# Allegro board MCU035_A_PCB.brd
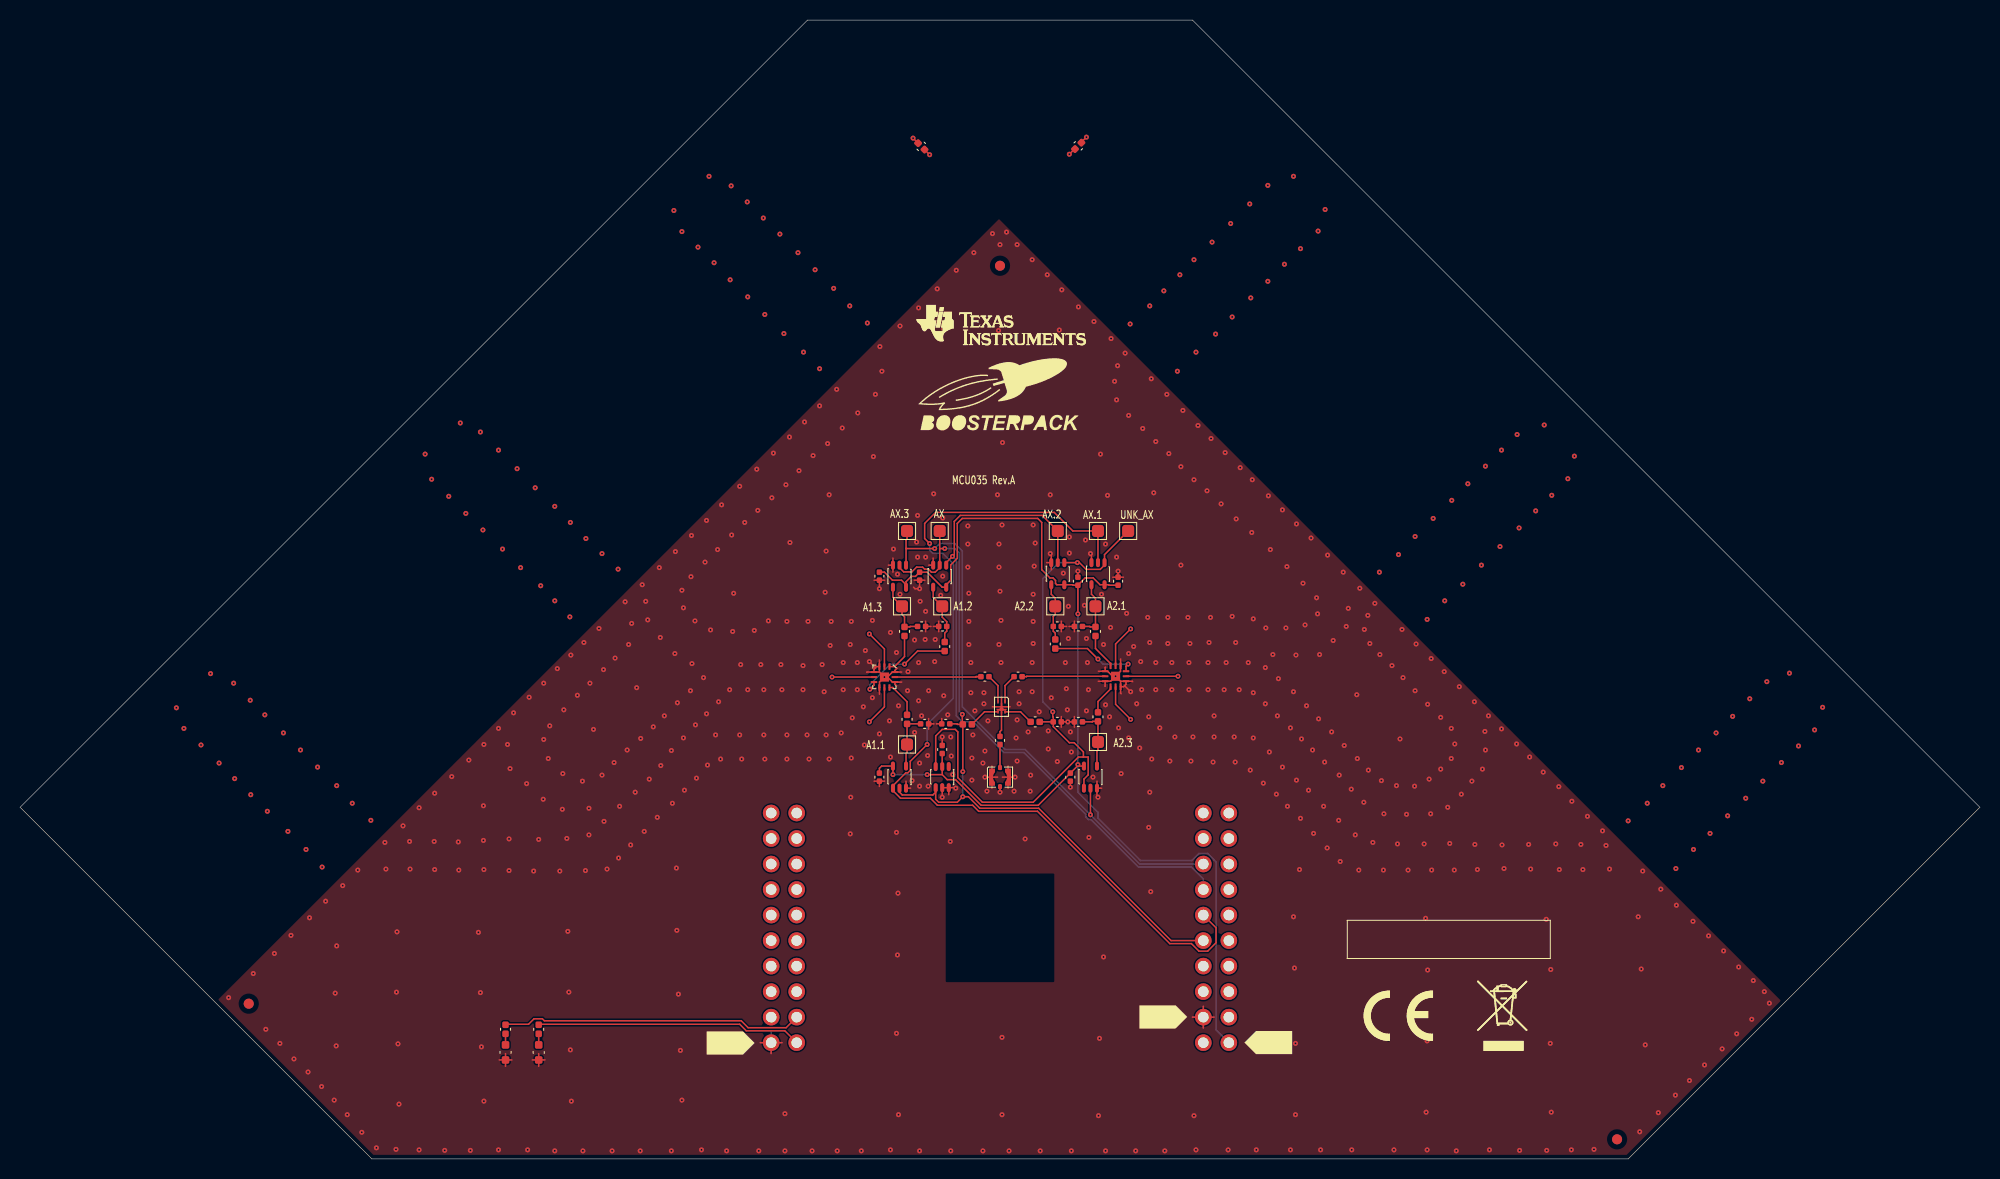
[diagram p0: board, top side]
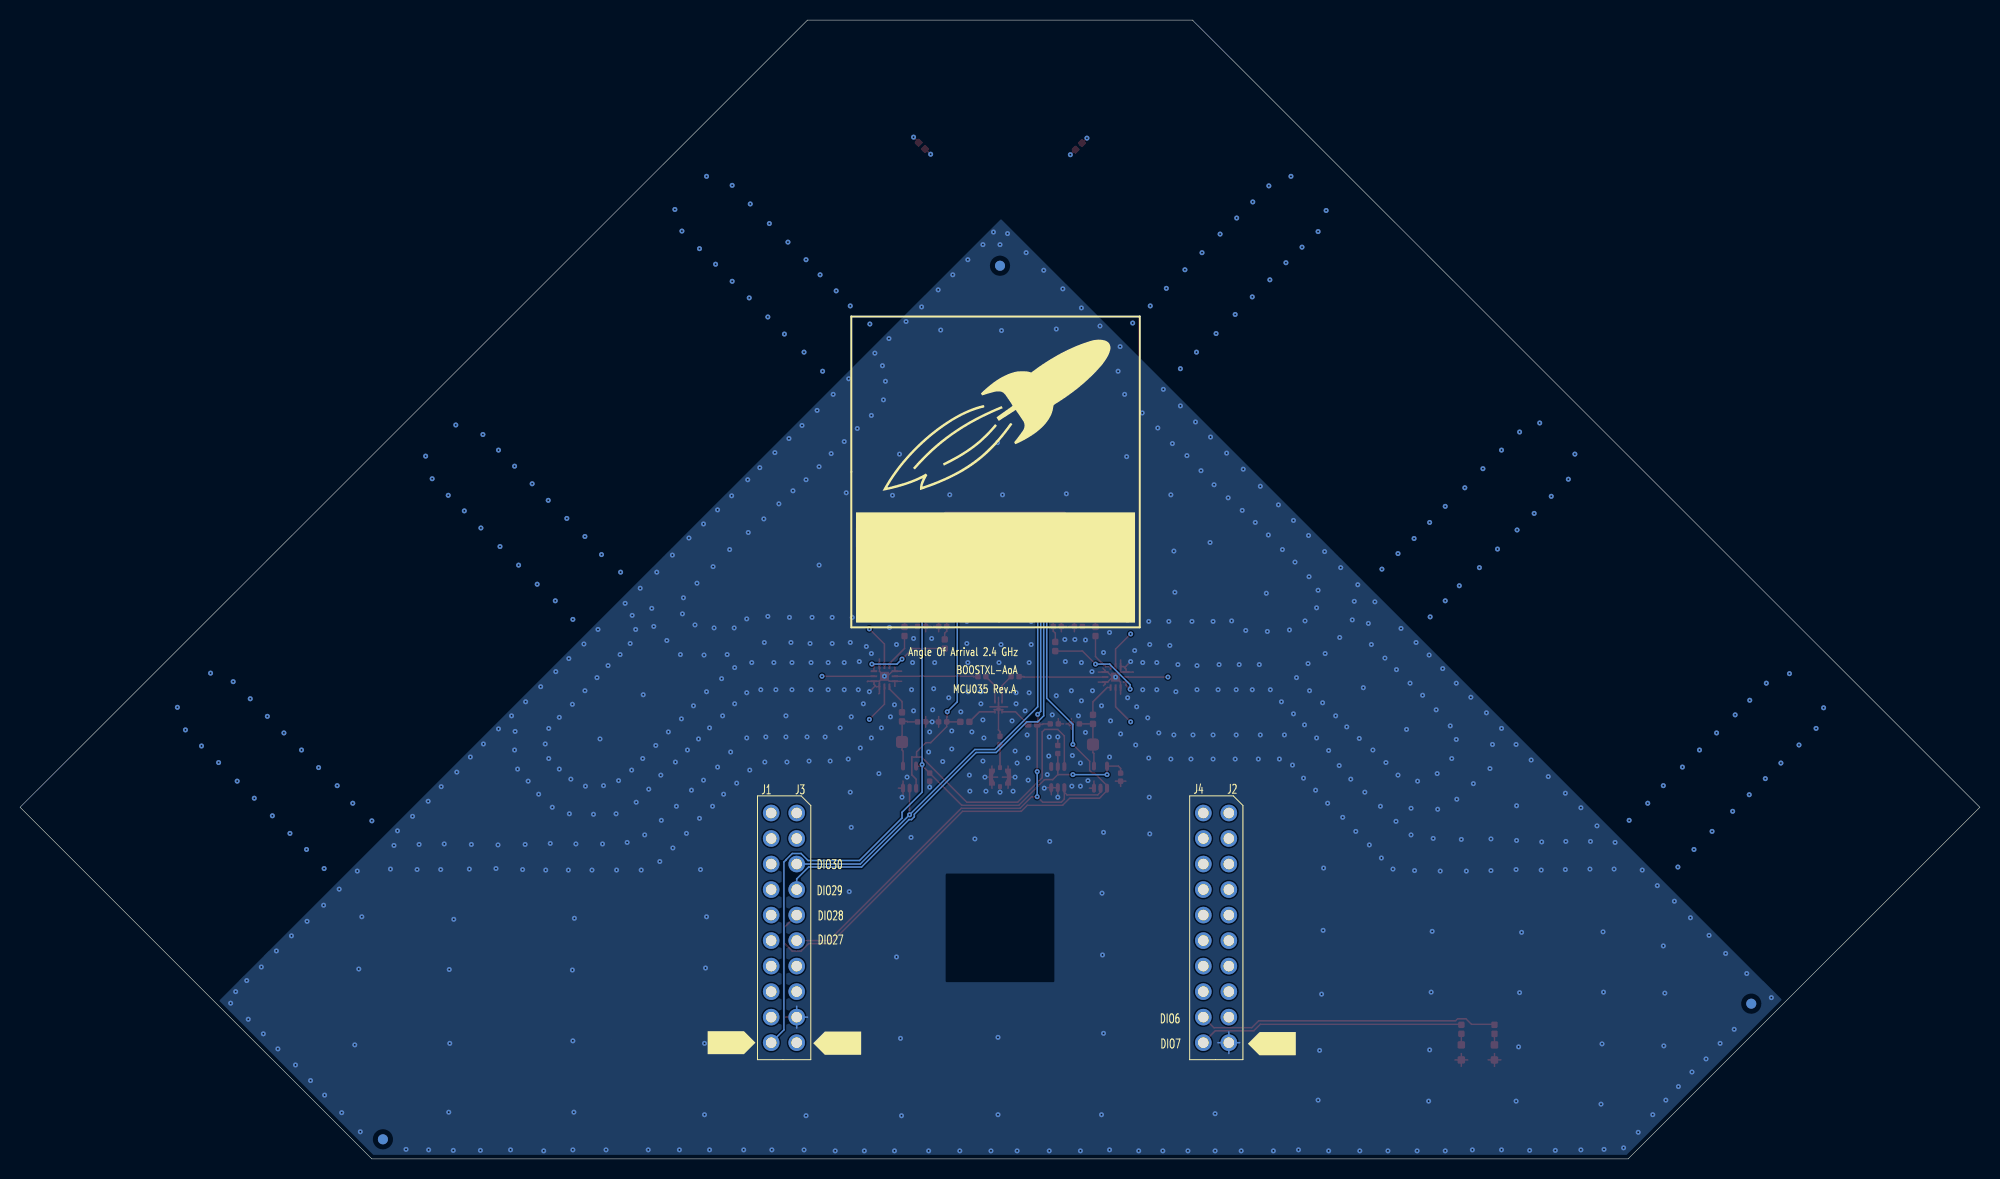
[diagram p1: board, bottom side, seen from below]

Outline 195 x 113.35 mm; copper layers: TOP, LAYER2, LAYER3, LAYER4, LAYER5, BOTTOM. Coordinates in mm from the lower left corner of the outline.
Outline path: 0,35 78.35,113.35 116.65,113.35 195,35 160,0 35,0 0,35

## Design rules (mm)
constraint set DEFAULT: min track width 0.15
net group AX: nets ANT1 ANT2 ANT3 ANT4 ANT5 ANT6

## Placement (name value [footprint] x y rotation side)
A1.1  TP_1.2MM_1.2MM_SMD  [TPS120]  88.25 41.25 0 top
A1.2  TP_1.2MM_1.2MM_SMD  [TPS120]  91.75 55 0 top
A1.3  TP_1.2MM_1.2MM_SMD  [TPS120]  87.75 55 0 top
A2.1  TP_1.2MM_1.2MM_SMD  [TPS120]  107 55 0 top
A2.2  TP_1.2MM_1.2MM_SMD  [TPS120]  103 55 0 top
A2.3  TP_1.2MM_1.2MM_SMD  [TPS120]  107.25 41.5 0 top
AX  TP_1.2MM_1.2MM_SMD  [TPS120]  91.5 62.5 0 top
AX.1  TP_1.2MM_1.2MM_SMD  [TPS120]  107.25 62.5 0 top
AX.2  TP_1.2MM_1.2MM_SMD  [TPS120]  103.25 62.5 0 top
AX.3  TP_1.2MM_1.2MM_SMD  [TPS120]  88.25 62.5 0 top
C1  12pF  [CAPC1005X60L]  91.7 43.3 0 top
C2  12pF  [CAPC1005X60L]  103.6 43.5 180 top
C3  12pF  [CAPC1005X60L]  104.9 53 0 top
C4  12pF  [CAPC1005X60L]  103.6 53 180 top
C5  12pF  [CAPC1005X60L]  104.9 43.5 0 top
C6  12pF  [CAPC1005X60L]  89.6 43.3 0 top
C7  12pF  [CAPC1005X60L]  92.2 53 180 top
C8  12pF  [CAPC1005X60L]  89.3 53 0 top
C9  100nF  [CAPC1005X60L]  91.75 40.35 90 top
C10  100nF  [CAPC1005X60L]  109.25 57.1 90 top
C11  100nF  [CAPC1005X60L]  105.25 57.1 90 top
C12  100nF  [CAPC1005X60L]  104.5 38.4 270 top
C13  100nF  [CAPC1005X60L]  85.5 37.6 90 top
C14  100nF  [CAPC1005X60L]  89.5 58.4 270 top
C15  100nF  [CAPC1005X60L]  85.5 58.4 270 top
C16  12pF  [CAPC1005X60L]  97.5 41.25 90 top
C17  12pF  [CAPC1005X60L]  95.6 48 0 top
C18  12pF  [CAPC1005X60L]  99.7 48 180 top
FIDU1  FIDU_1MM  [FID100X115]  22.75 15.45 0 top
FIDU2  FIDU_1MM  [FID100X115]  97.5 88.9 0 top
FIDU3  FIDU_1MM  [FID100X115]  158.9 1.95 0 top
FIDU4  FIDU_1MM  [FID100X115]  97.5 88.9 180 bottom
FIDU5  FIDU_1MM  [FID100X115]  22.75 15.45 180 bottom
FIDU6  FIDU_1MM  [FID100X115]  158.9 1.95 180 bottom
J1  SSQ-110-23-L-D  [SAMTEC_SSQ11023LD_A2B]  117.73 34.43 0 bottom
J2  SSQ-110-23-L-D  [SAMTEC_SSQ11023LD_A2B]  74.73 34.43 0 bottom
LBL1  -  [LABEL_BOOSTERPACK_ROCKET]  97.33 76.12 0 top
LBL2  -  [LABEL_FOR_EVALUATION_ONLY]  132.2 20.1 0 top
LBL4  TI_LOGO  [TI_LOGO_1]  90.17 85 0 top
LBL6  CE_label  [CE_LABEL]  136.3 11.75 0 top
LBL7  TRASH_7mm  [TRASH_7MM]  145.6 10.75 0 top
LED_GREEN  LPL296-J2L2-25  [LEDC1707X65L]  51.6 9.85 90 top
LED_RED  LS L296-P2Q2-1  [LEDC1708X67L]  48.3 9.85 90 top
NOREF  -  []  92.5 20.7 0 top
NOREF#2  -  []  94.03 0 90 top
NOREF#3  -  []  0 35 0 top
NOREF#4  -  []  78.35 113.35 0 top
NOREF#5  -  []  -23 -54.65 0 top
NOREF#6  -  []  160 0 0 top
NOREF#7  -  []  35 0 0 top
NOREF#8  -  []  0 35 0 top
NOREF#9  -  []  94.29 18 90 top
NOREF#10  -  []  66.2 5.95 0 top
NOREF#11  -  []  116.65 113.35 0 top
NOREF#12  -  []  121.7 13.5 0 top
NOREF#13  -  []  125.7 10.25 0 top
NOREF#14  -  []  -22.6 -55 0 top
NOREF#15  -  []  35 0 90 top
NOREF#16  -  []  0 35 0 top
NOREF#17  -  []  102.39 18.19 0 top
NOREF#18  -  []  0 35 0 top
NOREF#19  -  []  112.3 52.9 180 bottom
NOREF#20  -  []  117.8 9.1 180 bottom
NOREF#21  -  []  74.55 9.05 180 bottom
NOREF#22  -  []  126.65 10.35 180 bottom
P1  MM5829-2700  [MURATA_MM58292700RJ4_A2N]  97.5 38.95 270 top
R3  1k  [RESC1005X40A2N]  107 52.95 270 top
R4  1k  [RESC1005X40A2N]  103 51.7 270 top
R5  1k  [RESC1005X40A2N]  107.25 43.55 90 top
R6  1k  [RESC1005X40A2N]  88.25 43.3 90 top
R7  1k  [RESC1005X40A2N]  92 51.45 270 top
R8  1k  [RESC1005X40A2N]  88 52.95 270 top
R9  1k  [RESC1005X40A2N]  101.45 43.5 180 top
R10  1k  [RESC1005X40A2N]  93.8 43.25 0 top
R11  180  [RESC1005X40A2N]  51.6 12.45 90 top
R12  220  [RESC1005X40A2N]  48.3 12.45 90 top
R13  220  [RESC1005X40A2N]  89.35 101.1 315 top
R14  220  [RESC1005X40A2N]  105.6 101.15 225 top
U1  SKY13323-378  [QFNFC35P100X100X50-6N]  98 45.5 180 top
U2  SKY13408-465LF  [QFNFC50P200X200X65-13A2N]  86.5 49 180 top
U3  SKY13408-465LF  [QFNFC50P200X200X65-13A2N]  108.5 47 0 top
U5  SN74LVC2GU04  [SOT65P210X110-6N]  91.1 36.95 0 top
U6  SN74LVC1G08DCK  [SOT65P210X110-5N]  107.9 59.35 180 top
U7  SN74LVC1G08DCK  [SOT65P210X110-5N]  103.9 59.35 180 top
U8  SN74LVC1G08DCK  [SOT65P210X110-5N]  105.85 36.9 0 top
U9  SN74LVC1G08DCK  [SOT65P210X110-5N]  86.85 36.9 0 top
U10  SN74LVC1G08DCK  [SOT65P210X110-5N]  92.15 59.1 180 top
U11  SN74LVC1G08DCK  [SOT65P210X110-5N]  88.15 59.1 180 top
UNK_AX  TP_1.2MM_1.2MM_SMD  [TPS120]  110.25 62.5 0 top

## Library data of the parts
A1.1-A1.3 A2.1-A2.3 AX AX.1-AX.3 UNK_AX = TEST_POINT
C1-C18 = CAPACITOR: alternate symbols: (CAPC1005X60L,CAPC1005X60M)
FIDU1-FIDU6 = FIDMARK
J1 J2 = CONN_HEADER_2X10_J_S_V1: User Part Number: #PN; alternate symbols: (SAMTEC_SSQ11023LD_A2C,SAMTEC_SSQ11023LD_A2A)
LBL1 = LABEL_LAUNCHPAD_ROCKET: User Part Number: #PN
LBL2 = LABEL_FOR_EVALUATOIN_ONLY: User Part Number: #PN
LBL4 = TI_LOGO_V1
LBL6 = CE_LABEL
LBL7 = TRASH_V2: User Part Number: #PN
LED_GREEN = LED: alternate symbols: (LEDC1707X65L,LEDC1707X65M)
LED_RED = LED: alternate symbols: (LEDC1708X67L,LEDC1708X67M)
P1 = CONN_COAX_1_1_P_2MH_V1: User Part Number: #PN; alternate symbols: (MURATA_MM58292700RJ4_A2L,MURATA_MM58292700RJ4_A2M)
R3-R14 = RESISTOR: User Part Number: #PN; alternate symbols: (RESC1005X40A2L,RESC1005X40A2M)
U1 = IC_SWITCH_SKY13323-378L_QFN6: User Part Number: #PN
U2 U3 = IC_RF_SKY13408-465LF_QFN12_V1: User Part Number: #PN; alternate symbols: (QFNFC50P200X200X65-13A2L,QFNFC50P200X200X65-13A2M)
U5 = IC_LOGIC_SN74LVC2GU04_SC70_V1: alternate symbols: (SOT65P210X110-6L,SOT65P210X110-6M)
U6-U11 = IC_LOGIC_SN74LVC1G08_SC70-5_V1: alternate symbols: (SOT65P210X110-5L,SOT65P210X110-5M)

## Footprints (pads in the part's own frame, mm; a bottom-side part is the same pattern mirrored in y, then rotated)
CAPC1005X60L
  custom 0.135x0.135 smd: 1(0,0) 2(0.8,0)
CE_LABEL
  oval 0.025x0.051 smd: 1(-0.15,0.1)
FID100X115
  round 1 smd: 1(0,0)
LEDC1707X65L
  custom 0.188x0.188 smd: 1(0,0) 2(1.5,0)
LEDC1708X67L
  custom 0.188x0.188 smd: 1(0,0) 2(1.5,0)
MURATA_MM58292700RJ4_A2N
  custom 0.1x0.1 smd: 1(0,0) 2(1.9,0)
  custom 0.15x0.15 smd: M1(0.95,-0.8) M2(0.95,0.8)
QFNFC35P100X100X50-6N
  custom 0.037x0.037 smd: 1(0,0) 3(0.7,0) 4(0.7,1) 5(0.35,1) 6(0,1)
  custom 0.201x0.201 smd: 2(0.35,0.5)
QFNFC50P200X200X65-13A2N
  custom 0.05x0.05 smd: 1(0,0) 2(0.5,0) 3(1,0) 4(1.54,0.54) 5(1.54,1.04) 6(1.54,1.54) 7(1,2.08) 8(0.5,2.08) 9(0,2.08) 10(-0.54,1.54) 11(-0.54,1.04) 12(-0.54,0.54)
  rect 0.9x0.9 smd: 13(0.5,1.04)
RESC1005X40A2N
  custom 0.16x0.16 smd: 1(0,0) 2(0.9,0)
SAMTEC_SSQ11023LD_A2B
  round 1.65 hole 1.05: 1(0,0) 2(2.54,0) 3(0,2.54) 4(2.54,2.54) 5(0,5.08) 6(2.54,5.08) 7(0,7.62) 8(2.54,7.62) 9(0,10.16) 10(2.54,10.16) 11(0,12.7) 12(2.54,12.7) 13(0,15.24) 14(2.54,15.24) 15(0,17.78) 16(2.54,17.78) 17(0,20.32) 18(2.54,20.32) 19(0,22.86) 20(2.54,22.86)
SOT65P210X110-5N
  oval 0.4x0.9 smd: 1(0,0) 2(0.65,0) 3(1.3,0) 4(1.3,2.2) 5(0,2.2)
SOT65P210X110-6N
  oval 0.4x0.9 smd: 1(0,0) 2(0.65,0) 3(1.3,0) 4(1.3,2.1) 5(0.65,2.1) 6(0,2.1)
TPS120
  custom 0.3x0.3 smd: 1(0,0)

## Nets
GND: C1.1 C2.1 C3.1 C4.1 C5.1 C6.2 C7.2 C8.2 C9.2 C10.2 C11.2 C12.2 C13.1 C14.2 C15.2 J1.17 J2.19 LED_GREEN.1(C) LED_RED.1(C) P1.2 P1.M1 P1.M2 R13.2 R14.2 U1.2 U2.3 U2.4 U2.7 U2.10 U2.12 U2.13 U3.3 U3.4 U3.7 U3.10 U3.12 U3.13 U5.2 U5.3 U6.3 U7.3 U8.3 U9.3 U10.3 U11.3
GND2: R13.1
GND3: R14.1
VDDS: C9.1 C10.1 C11.1 C12.1 C13.2 C14.1 C15.1 J1.20 U5.5(VCC) U6.5 U7.5 U8.5 U9.5 U10.5 U11.5
_AX: C2.2 R9.1 U5.6 U6.1 U7.1 U8.1 UNK_AX.1
ANT1: U2.8
ANT2: U2.5
ANT3: U2.2
ANT4: U3.8
ANT5: U3.5
ANT6: U3.2
AX: AX.1 C1.2 J1.11 R10.1 U5.1 U9.2 U10.2 U11.2
AX.1: AX.1.1 J1.9 U6.2 U9.1
AX.2: AX.2.1 J1.7 U7.2 U10.1
AX.3: AX.3.1 J1.5 U8.2 U11.1
DIO6_RLED: J2.18 R12.2
DIO7_GLED/LED_PWM: J2.20 R11.2
N425181: C16.1 P1.1
N425288: C16.2 U1.5
N426207: C18.2 U1.1
N426219: C17.2 U1.3
N426254: C18.1 U3.11
N426301: C17.1 U2.11
N1430973: R3.2 U3.9
N1430985: A2.1.1 C3.2 R3.1 U6.4(Y)
N1431032: A2.2.1 C4.2 R4.1 U7.4(Y)
N1431076: A2.3.1 C5.2 R5.1 U8.4(Y)
N1431119: R4.2 U3.6
N1431128: R5.2 U3.1(V3)
N1436088: A1.3.1 C8.1 R8.1 U11.4(Y)
N1436095: A1.2.1 C7.1 R7.1 U10.4(Y)
N1436102: A1.1.1 C6.1 R6.1 U9.4(Y)
N1436751: R6.2 U2.9
N1436763: R7.2 U2.6
N1436767: R8.2 U2.1(V3)
N1437911: R9.2 U1.6
N1438003: R10.2 U1.4(VCTL2)
N1442122: LED_RED.2 R12.1
N1442126: LED_GREEN.2 R11.1

Pads without a net: FIDU1 1; FIDU2 1; FIDU3 1; FIDU4 1; FIDU5 1; FIDU6 1; J1 1 2 3 4 6 8 10 12 13 14 15 16 18 19; J2 1 2 3 4 5 6 7 8 9 10 11 12 13 14 15 16 17; LBL6 1; U5 4

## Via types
v1: diameter 0.5, hole 0.2, TOP to BOTTOM, 795 vias

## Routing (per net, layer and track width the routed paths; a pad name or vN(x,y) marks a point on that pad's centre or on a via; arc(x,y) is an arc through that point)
GND: length 106.5
  TOP w0.15: C5.1 104.9,44.02 ; C5.1 104.9,42.98 ; C5.1 v1(104.25,43.5) C2.1 ; 86.85,58.4 U11.3 ; U11.3 86.85,59.8 ; U11.3 86.4,59.1 ; v1(86,47.96) 85.51,47.47 85.51,46.93 U2.7 ; v1(86,47.96) 86,47.66 ; v1(86,47.96) 85.5,48.46 ; v1(86,47.96) 86.3,47.96 ; v1(110.5,46.5) 109.91,47.09 109.91,47.11 ; 109.55,46.3 109.5,46.35 U3.3 ; 85.5,47.16 U2.7 ; U2.7 85.5,46.25 ; 117.73,13.03 J1.17 ; J1.17 117.73,15.19 ; J1.17 118.81,14.11 ; J1.17 116.65,14.11 ; U3.12 107.97,47.55 108.51,47.55 v1(109,48.04) ; U3.12 107.96,47.06 107.95,47.05 ; U3.12 107.29,47.54 ; 102.15,59.35 U7.3 ; U7.3 102.6,60.15 v1(102.5,60.25) ; U7.3 102.6,58.65 ; U2.10 87.04,47.26 87.2,47.1 ; U2.10 87.71,47.46 ; U2.10 86.8,47.46 86.3,47.96 ; U2.12 86.8,48.46 86.3,47.96 ; U2.12 87.71,48.46 ; U2.12 87.04,48.61 87.26,48.84 ; U2.4 84.96,48.76 85.08,48.88 ; U2.4 84.26,48.46 84.25,48.45 ; U2.4 85.5,48.46 ; 50.97,9.85 LED_GREEN.1 ; LED_GREEN.1 52.23,9.85 ; LED_GREEN.1 51.6,9.22 ; LED_GREEN.1 51.6,10.48 ; R13.2 v1(90.5,99.95) ; P1.M2 98.3,39.1 ; P1.M2 v1(99,38) ; P1.M2 98.3,36.9 ; P1.M2 97.75,38 ; C10.2 v1(109.25,58.5) ; C10.2 108.73,57.9 ; C10.2 109.77,57.9 ; U8.3 107.15,37.6 ; U8.3 107.15,36.1 v1(107.25,36) ; U8.3 107.6,36.9 ; v1(84.5,49.5) 85.08,48.92 85.08,48.88 ; C4.1 104.13,53 ; C4.1 103.6,53.52 ; C4.1 103.6,52.48 ; 109.5,47.54 v1(109,48.04) ; 109.5,47.54 U3.4 ; 109.5,47.54 U3.3 ; v1(109,48.04) 109.49,48.53 109.49,49.07 U3.7 109.5,49.75 ; v1(109,48.04) 108.7,48.04 108.2,48.54 U3.10 ; P1.M1 v1(96,38) ; P1.M1 96.7,36.9 ; P1.M1 96.7,39.1 ; P1.M1 97.25,38 ; U3.4 110.66,47.54 110.7,47.5 ; U3.4 110.04,47.24 109.91,47.11 ; 108,48.95 107.96,48.91 U3.10 ; 90.4,59.1 U10.3 90.85,59.8 ; 85.5,48.46 U2.3 ; U2.3 85.5,49.65 ; U2.3 85.2,49 85.08,48.88 ; C3.1 104.9,53.52 ; C3.1 104.9,52.48 ; C3.1 104.37,53 ; R14.2 104.91,100.51 v1(104.4,100) ; 91.4,52.48 C7.2 ; C7.2 90.87,53 ; C7.2 91.4,53.52 ; J2.19 75.81,11.57 ; J2.19 73.65,11.57 ; J2.19 74.73,10.49 ; C8.2 90.1,53.52 ; C8.2 90.63,53 ; C8.2 90.1,52.48 ; C15.2 v1(85.5,56.75) ; C15.2 86.02,57.6 ; C15.2 84.98,57.6 ; U1.2 97.65,45.95 ; U1.2 96.75,45 ; U1.2 98.5,45 ; C11.2 v1(105.25,58.5) ; 88.9,56.9 89.05,56.75 v1(89.5,56.75) C14.2 ; v1(91.75,36) U5.2 U5.3 ; U5.3 92.4,36.25 ; U5.3 92.85,36.95 ; LED_RED.1 48.93,9.85 ; LED_RED.1 48.3,9.22 ; LED_RED.1 47.67,9.85 ; LED_RED.1 48.3,10.48 ; U3.10 107.29,48.54 ; C13.1 86.02,37.6 ; C13.1 84.98,37.6 ; C13.1 85.5,37.07 ; 109.91,47.11 109.8,47 U3.3 ; C6.2 90.4,43.82 ; C6.2 90.4,42.78 ; C6.2 90.93,43.3 ; C14.2 88.98,57.6 ; C14.2 90.02,57.6 ; C9.2 v1(91.75,42) ; C2.1 103.6,44.02 ; C2.1 103.6,42.98 ; 88.15,37.6 U9.3 88.6,36.9 ; 91.7,43.82 C1.1 91.17,43.3 ; U6.3 106.6,60.15 v1(106.5,60.25) ; C12.2 v1(104.5,37) ; P1.2 v1(97.5,36.5)
  LAYER2 w0.15: 74.73,10.49 J2.19 ; J2.19 75.81,11.57 ; J2.19 74.73,12.65 ; J2.19 73.65,11.57 ; J1.17 117.73,15.19 ; J1.17 117.73,13.03 ; J1.17 116.65,14.11 ; J1.17 118.81,14.11
  LAYER5 w0.15: J1.17 117.73,15.19 ; J1.17 117.73,13.03 ; J1.17 116.65,14.11 ; J1.17 118.81,14.11 ; 74.73,10.49 J2.19 ; J2.19 75.81,11.57 ; J2.19 73.65,11.57 ; J2.19 74.73,12.65
  BOTTOM w0.15: 116.65,14.11 J1.17 ; J1.17 117.73,13.03 ; J1.17 117.73,15.19 ; J2.19 75.81,11.57 ; J2.19 74.73,12.65 ; J2.19 73.65,11.57 ; J2.19 74.73,10.49
  vias: v1(15.55,44.9) v1(16.3,42.85) v1(18,41.2) v1(18.95,48.3) v1(19.8,39.4) v1(20.75,16.05) v1(21.25,47.35) v1(21.35,37.85) v1(22.9,45.65) v1(22.95,36.25) v1(23.2,18.45) v1(24.35,44.2) v1(24.45,12.9) v1(24.6,34.6) v1(25.3,20.45) v1(25.85,11.5) v1(26.2,42.4) v1(26.65,32.6) v1(26.95,22.25) v1(27.25,9.95) v1(27.9,40.7) v1(28.45,30.8) v1(28.65,8.65) v1(28.8,24) v1(29.6,39) v1(30.05,29.05) v1(30,7.2) v1(30.4,25.65) v1(31.25,5.85) v1(31.35,16.5) v1(31.5,37.15) v1(31.5,21.2) v1(31.45,11.25) v1(32.1,27.2) v1(32.55,4.4) v1(33.05,35.4) v1(33.6,28.75) v1(34,2.65) v1(34.9,33.7) v1(35.45,1.1) v1(36.3,31.5) v1(36.4,28.85) v1(37.4,0.95) v1(37.5,22.6) v1(37.45,16.6) v1(37.6,11.45) v1(37.7,5.45) v1(38.1,33.15) v1(38.75,31.6) v1(38.8,28.85) v1(39.7,34.95) v1(39.7,0.9) v1(40.3,70.15) v1(40.95,67.65) v1(41.25,36.4) v1(41.2,31.6) v1(41.25,28.8) v1(42.25,0.85) v1(42.65,65.95) v1(42.95,38.05) v1(43.6,31.55) v1(43.65,28.75) v1(43.8,73.25) v1(44.35,64.25) v1(44.65,39.7) v1(44.8,0.85) v1(45.6,22.55) v1(45.8,72.35) v1(45.8,16.55) v1(45.9,11.15) v1(46.05,62.6) v1(46.15,41.25) v1(46.1,35.15) v1(46.1,31.7) v1(46.15,28.8) v1(46.15,5.75) v1(47.6,70.55) v1(47.6,42.85) v1(47.6,0.9) v1(48,60.7) v1(48.5,41.25) v1(48.65,31.85) v1(48.65,28.7) v1(48.75,38.85) v1(49.1,44.4) v1(49.45,68.7) v1(49.8,58.85) v1(50.4,37.35) v1(50.5,0.9) v1(50.65,45.95) v1(51.1,28.65) v1(51.25,66.8) v1(51.6,31.8) v1(51.8,57.05) v1(52.05,35.8) v1(52.1,47.35) v1(52.1,41.75) v1(52.55,39.85) v1(52.7,43.1) v1(53.2,64.95) v1(53.2,55.55) v1(53.2,0.8) v1(53.45,48.8) v1(53.7,28.65) v1(54,38.35) v1(53.95,34.8) v1(54.1,44.7) v1(54.4,31.9) v1(54.5,22.65) v1(54.6,16.6) v1(54.7,53.95) v1(54.75,63.35) v1(54.8,50.15) v1(54.75,10.85) v1(54.85,5.75) v1(55.45,46.15) v1(55.95,37.6) v1(56,0.8) v1(56.1,51.4) v1(56.25,28.7) v1(56.3,61.75) v1(56.6,34.9) v1(56.6,32.25) v1(56.7,47.35) v1(57.05,42.75) v1(57.6,52.8) v1(57.9,60.25) v1(57.9,38.2) v1(58.05,48.7) v1(58.1,33.6) v1(58.4,28.85) v1(58.9,0.8) v1(59.1,39.45) v1(59.2,49.85) v1(59.5,58.7) v1(59.55,29.95) v1(59.65,35.1) v1(60.2,55.45) v1(60.4,40.7) v1(60.55,51.2) v1(60.85,53.3) v1(60.75,31.25) v1(61.2,36.5) v1(61.35,46.9) v1(61.7,0.8) v1(61.75,41.85) v1(61.9,57.15) v1(62.1,32.6) v1(62.25,55.5) v1(62.45,53.65) v1(62.6,37.8) v1(63,43) v1(63.4,34) v1(63.6,58.85) v1(63.7,51.9) v1(63.75,39.15) v1(64.1,44.1) v1(64.8,40.65) v1(64.8,0.8) v1(64.9,35.4) v1(65.05,94.4) v1(65.2,60.45) v1(65.15,50.3) v1(65.3,28.95) v1(65.35,22.75) v1(65.4,45.4) v1(65.5,16.4) v1(65.7,10.8) v1(65.85,92.3) v1(65.85,56.6) v1(65.85,5.85) v1(66,54.85) v1(66,41.9) v1(66.1,36.7) v1(66.7,46.6) v1(66.8,62.05) v1(66.75,57.95) v1(66.85,49.3) v1(67.15,53.55) v1(67.2,43.2) v1(67.3,37.9) v1(67.45,90.75) v1(67.8,0.9) v1(68,47.9) v1(68.15,59.4) v1(68.3,63.55) v1(68.3,44.3) v1(68.4,39.2) v1(68.55,97.8) v1(68.7,52.65) v1(69.05,89.2) v1(69.2,42.2) v1(69.4,60.65) v1(69.5,45.5) v1(69.7,39.8) v1(69.8,65.1) v1(70.3,0.8) v1(70.6,46.7) v1(70.65,87.5) v1(70.75,96.85) v1(70.8,62.1) v1(70.9,52.5) v1(71,56.3) v1(71.6,66.95) v1(71.6,42.2) v1(71.7,49.2) v1(71.8,39.8) v1(72.1,63.35) v1(72.35,95.25) v1(72.4,85.8) v1(72.4,46.7) v1(73.05,52.6) v1(73.3,68.65) v1(73.4,64.55) v1(73.5,0.8) v1(73.7,49.2) v1(73.95,93.65) v1(74,46.7) v1(74,42.2) v1(74.1,84.05) v1(74.1,39.8) v1(74.45,53.55) v1(74.8,65.8) v1(74.95,70.25) v1(75.6,92.05) v1(75.7,49.2) v1(75.8,46.7) v1(76,82.15) v1(76.1,4.5) v1(76.1,0.8) v1(76.2,67.1) v1(76.3,53.5) v1(76.3,42.2) v1(76.3,39.8) v1(76.55,71.85) v1(76.6,61.35) v1(77.4,90.2) v1(77.5,68.5) v1(77.9,49.1) v1(77.9,46.7) v1(77.95,80.3) v1(78.05,73.35) v1(78.3,42.2) v1(78.4,53.5) v1(78.5,39.8) v1(78.8,0.8) v1(78.9,70) v1(79.1,88.5) v1(79.55,78.65) v1(79.55,74.95) v1(79.8,49.2) v1(80,46.5) v1(80.1,56.4) v1(80.2,60.5) v1(80.2,42.2) v1(80.35,71.2) v1(80.5,66.1) v1(80.5,39.8) v1(80.6,51.1) v1(80.7,53.5) v1(80.95,86.65) v1(81.25,76.6) v1(81.3,0.8) v1(81.7,42.4) v1(81.8,72.75) v1(81.9,49.4) v1(81.9,46.7) v1(82.55,84.9) v1(82.6,51.2) v1(82.6,32.35) v1(82.7,53.5) v1(82.7,39.9) v1(82.65,36) v1(82.8,43.9) v1(83.35,74.25) v1(83.3,49.4) v1(83.3,46.7) v1(83.7,0.8) v1(83.9,45) v1(84,41.2) v1(84.1,50.6) v1(84.3,83.2) v1(84.8,53.6) v1(84.8,45.9) v1(84.9,69.9) v1(85.1,76.1) v1(85.55,80.85) v1(85.5,42.3) v1(85.75,78.4) v1(86.5,43.6) v1(86.6,52.4) v1(86.6,40) v1(86.6,0.9) v1(86.9,60.7) v1(87.2,50.4) v1(87.2,32.5) v1(87.2,12.5) v1(87.3,58.2) v1(87.35,26.45) v1(87.3,20.3) v1(87.4,45.1) v1(87.4,4.4) v1(87.55,82.9) v1(87.55,56.2) v1(88.35,48.5) v1(88.3,46.6) v1(88.75,37.65) v1(89,51.65) v1(89,42.45) v1(89.2,61.4) v1(89.3,64.05) v1(89.3,59.9) v1(89.4,84.7) v1(89.4,49.4) v1(89.4,45.6) v1(89.55,55.5) v1(89.5,39.4) v1(89.5,37.1) v1(89.5,0.8) v1(89.7,44.1) v1(90.05,51.7) v1(90.1,59.9) v1(90.1,54.5) v1(90.3,40.15) v1(90.35,37.1) v1(90.4,46.6) v1(90.9,66.2) v1(91.05,51.7) v1(91,49.5) v1(91.25,86.6) v1(91.6,56.1) v1(91.8,63.8) v1(91.8,58) v1(91.9,82.6) v1(91.9,46.1) v1(92.3,44.2) v1(92.55,31.6) v1(92.6,42) v1(92.6,0.8) v1(92.65,40.1) v1(92.8,38.25) v1(93.1,36.9) v1(93.15,88.45) v1(94.3,63) v1(94.3,61.2) v1(94.3,58.9) v1(94.4,56.3) v1(94.4,53.5) v1(94.4,51.2) v1(94.6,49.4) v1(94.6,46.4) v1(94.7,39.9) v1(94.7,37.7) v1(94.8,42.2) v1(94.9,90.2) v1(95,44.6) v1(95.8,39.4) v1(95.8,0.8) v1(95.9,46.4) v1(95.9,45.3) v1(96,40.6) v1(96.2,36.6) v1(96.3,43.6) v1(96.75,92.1) v1(97.25,66.1) v1(97.35,82.45) v1(97.4,61.2) v1(97.4,58.9) v1(97.4,51.2) v1(97.5,91) v1(97.5,56.5) v1(97.6,53.6) v1(97.6,49.4) v1(97.7,63.1) v1(97.7,12.1) v1(97.7,4.4) v1(97.75,71.3) v1(98.15,92.25) v1(98.4,0.8) v1(98.9,36.6) v1(99.1,41.9) v1(99.2,91) v1(99.2,43.7) v1(99.2,39.6) v1(99.4,46.5) v1(99.4,45.3) v1(100,31.85) v1(100.3,42.5) v1(100.55,38.2) v1(100.5,36.6) v1(100.7,89.5) v1(100.7,49.4) v1(100.7,46.5) v1(100.8,63.1) v1(100.8,56.2) v1(100.8,53.5) v1(100.8,51.3) v1(100.9,59) v1(101,61.3) v1(101.4,44.5) v1(101.5,0.8) v1(102.2,88) v1(102.3,42.6) v1(102.3,40.8) v1(102.5,66.1) v1(102.6,45.9) v1(103.2,39.55) v1(103.4,82.5) v1(103.65,86.5) v1(103.8,58.3) v1(104,49.4) v1(104.1,46.8) v1(104.2,44.7) v1(104.3,55) v1(104.3,51.8) v1(104.4,61.9) v1(104.4,60.3) v1(104.5,42.5) v1(104.6,40.5) v1(104.6,0.8) v1(105.3,84.8) v1(105.9,55.1) v1(106,61.6) v1(106.1,51.8) v1(106.1,44.6) v1(106.2,49.4) v1(106.3,46.7) v1(106.35,32) v1(106.85,83.35) v1(106.75,38) v1(107.3,4.3) v1(107.4,12) v1(107.5,70.15) v1(107.6,56.2) v1(107.8,51.2) v1(107.8,20.1) v1(108,61.2) v1(108,45.2) v1(108,0.8) v1(108.2,66.05) v1(108.4,44) v1(108.55,81.65) v1(108.5,52.9) v1(108.9,77.4) v1(109.1,75.55) v1(109.1,59.9) v1(109.2,78.95) v1(109.3,42.9) v1(109.55,38.35) v1(109.95,80.2) v1(110.1,54.3) v1(110.3,74) v1(110.3,50.3) v1(110.3,41.9) v1(110.45,83.1) v1(110.8,51) v1(111,0.8) v1(111.1,45.3) v1(111.4,40.9) v1(111.5,49.5) v1(111.6,46.7) v1(111.7,72.7) v1(112.2,53.9) v1(112.3,44) v1(112.3,33) v1(112.4,84.9) v1(112.4,51.4) v1(112.4,36.5) v1(112.55,77.65) v1(112.5,26.6) v1(112.6,39.8) v1(112.8,66.3) v1(113,71.4) v1(113,49.4) v1(113,46.7) v1(113.4,42.9) v1(113.8,86.4) v1(113.9,0.8) v1(114.1,76.1) v1(114.2,53.9) v1(114.2,51.3) v1(114.3,70.2) v1(114.4,39.6) v1(114.6,49.4) v1(114.6,46.7) v1(114.9,42) v1(115.15,78.4) v1(115.4,88) v1(115.5,68.9) v1(115.5,59.1) v1(115.7,74.5) v1(116.2,53.9) v1(116.3,49.4) v1(116.3,46.7) v1(116.4,51.3) v1(116.5,39.6) v1(116.7,42) v1(116.8,89.5) v1(116.8,67.6) v1(116.8,4.3) v1(117,80.3) v1(117,0.9) v1(117.2,73) v1(118.1,66.5) v1(118.2,49.4) v1(118.2,46.7) v1(118.3,51.4) v1(118.5,71.7) v1(118.45,53.9) v1(118.6,91.25) v1(118.7,39.5) v1(118.8,44.1) v1(118.8,42) v1(118.95,82.1) v1(119.5,65.2) v1(119.8,46.7) v1(119.9,70.3) v1(120,49.4) v1(120.2,0.9) v1(120.45,93.1) v1(120.6,83.8) v1(120.6,54) v1(120.8,42) v1(120.9,39.5) v1(121,63.7) v1(120.95,51.4) v1(121.3,46.7) v1(121.4,68.8) v1(122.2,49.4) v1(122.35,95.05) v1(122.4,38.7) v1(122.45,85.7) v1(122.55,62.35) v1(122.6,67.6) v1(122.7,53.75) v1(122.7,46.4) v1(122.7,41.9) v1(123,0.9) v1(123.7,37.4) v1(123.95,52.85) v1(123.9,48.9) v1(123.9,45.3) v1(124.15,96.9) v1(124.15,87.35) v1(124.2,66) v1(124.3,40.5) v1(124.4,60.65) v1(124.65,50.2) v1(125,36.3) v1(125.1,44.1) v1(125.2,47.8) v1(125.6,64.6) v1(125.6,39) v1(125.8,89.05) v1(125.95,52.85) v1(126.05,58.95) v1(126.1,35.1) v1(126.4,42.9) v1(126.4,0.9) v1(126.7,97.8) v1(126.7,46.5) v1(126.7,24.1) v1(126.8,19) v1(126.95,50.15) v1(126.9,11.5) v1(126.9,4.4) v1(127,63.2) v1(127,37.7) v1(127.3,28.8) v1(127.4,90.6) v1(127.4,33.9) v1(127.5,41.8) v1(127.65,57.3) v1(127.85,53.15) v1(128,45.1) v1(128.2,36.7) v1(128.45,61.8) v1(128.6,40.7) v1(128.7,32.4) v1(129,55.85) v1(129.1,54.25) v1(129.15,92.35) v1(129.2,43.8) v1(129.3,50.2) v1(129.4,0.9) v1(129.7,35.1) v1(129.85,94.5) v1(129.8,39.5) v1(130.1,60.1) v1(130.05,30.95) v1(130.5,42.5) v1(130.65,51.6) v1(131.25,38.2) v1(131.2,33.7) v1(131.35,29.6) v1(131.65,58.4) v1(131.75,41.15) v1(131.95,53) v1(132.15,54.8) v1(132.45,36.8) v1(132.5,0.9) v1(132.85,32.25) v1(133,46.2) v1(133.05,39.85) v1(133.2,28.75) v1(133.3,56.8) v1(133.7,35.5) v1(133.75,52.7) v1(134.1,54.1) v1(134.15,38.7) v1(134.3,51.3) v1(134.6,31.5) v1(134.8,55.3) v1(135.25,58.4) v1(135.3,50.2) v1(135.45,37.65) v1(135.7,34.35) v1(135.65,28.75) v1(136.5,49.1) v1(136.7,0.9) v1(136.95,37.15) v1(137.05,31.35) v1(137.15,60.15) v1(137.3,41.8) v1(137.5,52.7) v1(137.6,47.9) v1(137.95,34.3) v1(138.1,28.75) v1(138.8,61.95) v1(138.8,46.6) v1(138.75,37.1) v1(138.9,51.25) v1(139.7,31.35) v1(139.85,23.95) v1(139.9,4.65) v1(140,53.7) v1(140,11.75) v1(140,0.9) v1(140.05,45.25) v1(140.05,18.8) v1(140.2,37.8) v1(140.35,34.35) v1(140.4,49.8) v1(140.45,28.75) v1(140.6,63.75) v1(141.35,43.95) v1(141.35,38.8) v1(141.7,48.5) v1(141.75,55.55) v1(142.05,35) v1(142.25,31.4) v1(142.45,65.55) v1(142.4,42.85) v1(142.4,39.85) v1(142.7,28.75) v1(142.75,41.3) v1(142.9,0.8) v1(143.2,47) v1(143.4,36.3) v1(143.55,57.2) v1(144.05,67.2) v1(144.45,37.6) v1(144.7,45.5) v1(144.75,31.3) v1(145,28.8) v1(145.4,59.1) v1(145.5,38.8) v1(145.8,68.95) v1(145.75,42.55) v1(145.8,40.7) v1(146.1,44.1) v1(146.2,0.9) v1(147.25,60.95) v1(147.4,70.55) v1(147.4,42.8) v1(147.45,31.25) v1(147.65,28.9) v1(148.95,72.1) v1(148.9,41.3) v1(149.15,62.8) v1(149.2,0.85) v1(150.1,31.3) v1(150.2,40) v1(150.3,28.85) v1(150.8,64.5) v1(151.55,38.5) v1(151.65,73.05) v1(151.85,23.85) v1(151.9,0.85) v1(152.25,11.5) v1(152.3,18.85) v1(152.35,4.65) v1(152.4,66.05) v1(152.8,31.35) v1(153.1,37.05) v1(153.15,28.8) v1(154,67.7) v1(154.35,0.9) v1(154.4,35.6) v1(154.65,69.95) v1(155.3,31.3) v1(155.5,28.8) v1(155.95,34.1) v1(156.6,0.95) v1(157.45,32.65) v1(157.8,31.2) v1(158.15,28.85) v1(160,33.65) v1(161,24.1) v1(161.15,2.7) v1(161.3,18.9) v1(161.45,28.65) v1(161.7,11.35) v1(161.9,35.4) v1(163,4.6) v1(163.25,26.85) v1(163.45,37.15) v1(164.7,6.35) v1(164.75,28.9) v1(164.8,25.25) v1(165.3,38.95) v1(166.1,7.8) v1(166.45,23.65) v1(166.5,30.8) v1(167,40.7) v1(167.6,9.35) v1(168,22.2) v1(168.15,32.4) v1(168.75,42.4) v1(169.35,10.95) v1(169.5,20.7) v1(169.9,34.15) v1(170.4,44.05) v1(170.8,12.45) v1(171,19.1) v1(171.7,35.9) v1(172.1,45.8) v1(172.3,13.9) v1(172.45,17.75) v1(173.4,37.6) v1(173.55,16.65) v1(173.8,47.5) v1(174.05,15.5) v1(175.25,39.45) v1(176.05,48.35) v1(176.95,41.1) v1(178.55,42.7) v1(179.35,44.95)
GND2: length 0.7
  TOP w0.15: R13.1 v1(88.85,101.6)
GND3: length 0.8
  TOP w0.15: v1(106.1,101.7) 105.6,101.2 R14.1
VDDS: length 121.6
  TOP w0.15: U8.5 105.19,39.1 ; 105.19,39.1 104.5,38.41 C12.1 104.5,38.4 101.31,35.2 95.62,35.2 93.08,37.75 92.25,37.75 91.75,38.25 ; 105.19,39.1 105.19,39.19 v1(105.25,39.25) ; C15.1 86,58.4 86.8,57.6 87.7,57.6 88.15,57.15 ; 88.15,57.15 88.15,57.45 88.68,57.98 89.09,57.98 89.5,58.39 C14.1 90.25,58.4 91.75,56.9 U10.5 92.15,57.15 92.6,57.6 92.6,59.13 93.25,59.78 93.25,63.25 93.75,63.75 101.25,63.75 101.65,63.35 101.65,58.65 102.47,57.83 102.78,57.83 103.03,57.58 103.03,57.28 103.15,57.15 U7.5 104.73,57.15 104.78,57.1 C11.1 ; 88.15,57.15 U11.5 ; v1(86.85,38.25) U9.5 85.72,39.1 85.5,38.88 C13.2 ; 91.75,38.25 v1(90.25,38.25) ; 91.75,38.25 U5.5 C9.1 ; C11.1 v1(105.25,54.25) ; C11.1 105.25,57.11 105.97,57.83 106.78,57.83 107.45,57.15 U6.5 108.3,57.15 108.35,57.1 C10.1
  BOTTOM w0.15: J1.20 119,12.84 119,29.55 118.78,29.77 118.78,29.78 118.17,30.4 117.3,30.4 116.59,29.7 111.47,29.7 107.25,33.92 107.25,34.5 105.25,36.5 v1(105.25,39.25) v1(105.25,54.25) ; v1(90.25,38.25) v1(86.85,38.25)
_AX: length 63.3
  TOP w0.15: U8.1 105.85,37.8 106.28,38.23 106.28,40 105.8,40 ; 105.8,40 105.8,40.5 104.88,41.42 104.4,41.42 102.8,43.03 C2.2 ; 105.8,40 105.3,40 100.8,35.5 95.75,35.5 93.3,37.95 93.3,42.5 93.05,42.75 91.75,42.75 91.1,42.1 U5.6 ; R9.1 C2.2 ; C2.2 102.8,43.97 102.75,44.02 v1(102.75,44.5) ; C2.2 102.85,43.5 ; UNK_AX.1 107.9,60.15 U6.1 107.9,59.1 107.47,58.67 106.08,58.67 105.4,59.35 v1(105.2,59.35) U7.1
  BOTTOM w0.15: v1(105.2,59.35) 103.35,59.35 101.75,57.75 101.75,45.5 v1(102.75,44.5)
ANT1: length 60.7
  TOP w0.15: v1(84.5,43.5) 86,45 U2.8
  LAYER4 w0.2: v1(84.5,43.5) 82,41 68.25,41 57.5,30.25 33.6,30.25 33.42,30.42
ANT2: length 60.6
  TOP w0.15: U2.5 v1(80.79,47.96)
  LAYER4 w0.2: 58.17,55.17 59.4,53.95 59.4,52.15 50.3,43.05 50.3,39.8 53.85,36.25 58.25,36.25 69.96,47.96 v1(80.79,47.96)
ANT3: length 60.6
  TOP w0.15: U2.2 86,50.75 v1(84.5,52.25)
  LAYER4 w0.2: 82.92,79.92 84.1,78.75 84.1,77.3 64.1,57.3 64.1,54.1 67.15,51.05 73.75,51.05 74.95,52.25 v1(84.5,52.25)
ANT4: length 60.6
  TOP w0.15: v1(110.5,52.75) 109,51.25 U3.8
  LAYER4 w0.2: 112.05,79.95 110.6,78.5 110.6,76.15 130.45,56.3 130.45,53.65 128.45,51.65 122.75,51.65 121.65,52.75 v1(110.5,52.75)
ANT5: length 60.7
  TOP w0.15: U3.5 v1(115.21,48.04)
  LAYER4 w0.2: 136.8,55.2 135.3,53.7 135.3,52.2 144.2,43.3 144.2,39.7 140.3,35.8 135.2,35.8 122.96,48.04 v1(115.21,48.04)
ANT6: length 60.6
  TOP w0.15: v1(110.5,43.75) 109,45.25 U3.2
  LAYER4 w0.2: v1(110.5,43.75) 113.5,40.75 122.25,40.75 132.8,30.2 161.25,30.2 161.53,30.48
AX: length 74.8
  TOP w0.15: U9.2 87.5,36.5 87.78,36.23 90.83,36.23 91.1,36.5 ; v1(93.75,44.25) 93.75,43.3 R10.1 ; U11.2 87.5,58.85 87.92,58.42 88.72,58.42 89.2,58.9 89.8,58.9 90,58.7 90.37,58.7 90.67,58.4 91.05,58.4 91.5,58.85 U10.2 91.5,60.75 ; R10.1 v1(93.8,38.55) ; R10.1 93.27,43.25 93.22,43.3 C1.2 ; U5.1 91.1,36.5 ; 91.1,36.5 91.1,35.8 91.4,35.5 93.25,35.5 v1(93.8,36.05) 94.35,36.05 95.5,34.9 101.35,34.9 114.52,21.73 J1.11 ; 91.5,60.75 AX.1 ; 91.5,60.75 v1(92,60.75)
  BOTTOM w0.15: v1(93.8,36.05) v1(93.8,38.55) ; v1(92,60.75) 93,60.75 93.45,60.3 93.45,44.55 v1(93.75,44.25)
AX.1: length 95
  TOP w0.15: v1(90.5,61.25) 90,61.75 90,63.25 91.1,64.35 102.9,64.35 104.75,62.5 AX.1.1 U6.2 ; v1(90.25,41.25) 88.58,39.58 88.58,38.67 88.33,38.42 88.12,38.42 86.85,37.15 U9.1 86.85,36.65 87.6,35.9 90.57,35.9 91.27,35.2 94.78,35.2 95.38,34.6 101.22,34.6 114.39,21.43 116.55,21.43 117.3,20.68 118.17,20.68 119,21.52 119,23 J1.9
  BOTTOM w0.15: v1(90.5,61.25) 90.5,60.58 90.8,60.28 91.8,60.28 92.85,59.23 92.85,45.85 90.25,43.25 v1(90.25,41.25)
AX.2: length 67.6
  TOP w0.15: U7.2 AX.2.1 101.7,64.05 93.55,64.05 92.95,63.45 92.95,60.15 v1(92.78,59.97) 92.15,59.35 U10.1
  BOTTOM w0.15: J1.7 117.73,27.87 116.55,29.05 111.28,29.05 106.55,33.77 106.3,33.77 106.03,34.05 106.03,34.3 99.88,40.45 97.88,40.45 94.83,43.5 93.75,43.5 93.15,44.1 93.15,59.6 v1(92.78,59.97)
AX.3: length 58.2
  TOP w0.15: 88.15,60.75 v1(91,60.75) ; 88.15,60.75 U11.1 ; 88.15,60.75 88.15,61.6 88.25,61.7 AX.3.1 ; v1(106.5,34.25) U8.2
  BOTTOM w0.15: v1(91,60.75) 91.5,61.25 93,61.25 93.75,60.5 93.75,45 98,40.75 100,40.75 v1(106.5,34.25) 111.4,29.35 J1.5
DIO6_RLED: length 30
  TOP w0.15: J2.18 76.22,13.06 72.44,13.06 71.75,13.75 52.16,13.75 51.96,13.95 51.14,13.95 50.59,13.4 48.35,13.4 R12.2
DIO7_GLED/LED_PWM: length 26.4
  TOP w0.15: R11.2 51.65,13.4 71.6,13.4 72.25,12.75 76.09,12.75 J2.20
N425181: length 2.3
  TOP w0.15: C16.1 P1.1
N425288: length 2.5
  TOP w0.15: U1.5 97.65,42.68 97.5,42.53 C16.2
N426207: length 2.9
  TOP w0.15: U1.1 98,47.11 98.89,48 C18.2
N426219: length 2.9
  TOP w0.15: U1.3 97.3,47.11 96.41,48 C17.2
N426254: length 8.3
  TOP w0.15: 99.65,48 C18.1 100.13,48 100.17,48.04 U3.11
N426301: length 8.6
  TOP w0.15: U2.11 95.08,47.96 95.12,48
  TOP w0.18: 95.12,48 C17.1
N1430973: length 3.6
  TOP w0.15: U3.9 108.5,49.31 107,50.81 R3.2
N1430985: length 5.7
  TOP w0.15: 105.65,53 C3.2 106.43,53 106.48,52.95 R3.1 A2.1.1 107,55.8 106.6,56.2 U6.4
N1431032: length 5.8
  TOP w0.15: R4.1 103,52.33 102.8,52.53 C4.2 102.8,54 103,54.2 A2.2.1 103,55.8 102.6,56.2 U7.4
N1431076: length 6.1
  TOP w0.15: U8.4 107.15,40.6 107.25,40.7 A2.3.1 R5.1 106.73,43.55 106.68,43.5 C5.2 105.65,43.5
N1431119: length 8.7
  TOP w0.15: v1(110.25,49.25) 110.04,49.04 U3.6 ; v1(107.25,49.75) 106.2,50.8 R4.2
  BOTTOM w0.15: v1(107.25,49.75) 107.75,49.25 v1(110.25,49.25)
N1431128: length 3.1
  TOP w0.15: U3.1 108.5,46.78 107.25,45.53 R5.2
N1436088: length 5.8
  TOP w0.15: 89.35,53 C8.1 88.57,53 88.52,52.95 R8.1 88,53.95 87.75,54.2 A1.3.1 86.85,55.9 U11.4
N1436095: length 6.1
  TOP w0.15: U10.4 90.85,55.9 A1.2.1 91.75,53.92 92.2,53.47 C7.1 92.2,52.53 92,52.33 R7.1
N1436102: length 5.6
  TOP w0.15: U9.4 88.15,40.35 88.25,40.45 A1.1.1 R6.1 C6.1
N1436751: length 3.6
  TOP w0.15: U2.9 86.83,46.92 88.25,45.5 R6.2
N1436763: length 10.2
  TOP w0.15: v1(84.55,46.75) 84.96,47.16 U2.6 ; v1(88,49.25) 89.3,50.55 R7.2
  BOTTOM w0.15: v1(88,49.25) 86.6,49.25 84.55,47.2 v1(84.55,46.75)
N1436767: length 4
  TOP w0.15: R8.2 88,50 87,49 U2.1
N1437911: length 3
  TOP w0.15: U1.6 99.55,44.5 100.55,43.5 R9.2
N1438003: length 3.1
  TOP w0.15: R10.2 94.7,43.25 95.95,44.5 U1.4
N1442122: length 1.1
  TOP w0.15: R12.1 LED_RED.2
N1442126: length 1.1
  TOP w0.15: R11.1 LED_GREEN.2

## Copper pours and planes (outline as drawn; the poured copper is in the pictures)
GND on LAYER2 (solid shape): 94.42,91.05 95.13,91.76 85.87,101.02 86.58,101.73 95.84,92.47 96.55,93.17 89.36,100.36 90.07,101.07 97.96,93.17 94.44,89.66 82.3,101.8 82.99,102.49
GND on LAYER2 (solid shape): 112.64,101.86 100.48,89.69 96.94,93.23 104.83,101.12 105.54,100.41 98.35,93.23 99.06,92.52 108.37,101.83 109.08,101.12 99.77,91.81 100.49,91.09 111.95,102.55
GND on LAYER2 (solid shape): 93.04,89.67 93.75,90.38 82.31,101.81 83,102.5 95.14,90.36 91.62,86.84 90.92,87.55 73.24,105.22 73.93,105.92 91.61,88.24 92.33,88.96 74.66,106.64 75.36,107.35
GND on LAYER2 (solid shape): 120.3,106.64 102.62,88.96 103.34,88.24 121.02,105.92 121.71,105.22 104.03,87.55 103.33,86.84 99.79,90.38 111.96,102.54 112.65,101.85 101.19,90.39 101.91,89.67 119.59,107.35
GND on LAYER2 (solid shape): 23.76,18.98 20.23,15.44 19.52,16.15 1.84,33.82 2.55,34.53 20.23,16.85 20.93,17.56 3.26,35.24 3.96,35.95 21.64,18.27 22.35,18.98 4.67,36.65 5.38,37.36
GND on LAYER2 (solid shape): 47.76,44.4 48.47,43.7 44.93,40.16 44.22,40.87 26.55,58.55 27.25,59.25 44.93,41.58 45.64,42.28 27.96,59.96 28.67,60.67 46.34,42.99 47.05,43.7 29.37,61.37 30.08,62.08
GND on LAYER2 (solid shape): 72.51,69.15 73.21,68.44 69.68,64.91 51.29,83.29 52,84 69.68,66.32 70.39,67.03 52.71,84.71 53.41,85.42 71.09,67.74 71.8,68.44 54.12,86.12 54.83,86.83
GND on LAYER2 (solid shape): 140.81,86.1 123.13,68.43 123.84,67.72 141.51,85.4 142.22,84.69 124.54,67.01 125.25,66.31 142.93,83.98 143.64,83.28 125.25,64.89 121.72,68.43 122.42,69.13 140.1,86.81
GND on LAYER2 (solid shape): 165.56,61.36 147.88,43.68 148.59,42.97 166.26,60.65 166.97,59.94 149.29,42.26 150,41.56 167.68,59.23 168.38,58.53 150,40.14 146.46,43.68 147.17,44.39 164.85,62.06
GND on LAYER2 (solid shape): 190.33,36.6 172.65,18.93 173.36,18.22 191.04,35.9 191.75,35.19 174.07,17.51 174.78,16.8 192.45,34.48 193.16,33.77 175.48,16.1 174.78,15.39 171.24,18.93 189.62,37.31
GND on LAYER2 (solid shape): 121.71,105.21 104.03,87.53 104.75,86.81 122.42,104.49 123.13,103.78 105.45,86.1 106.16,85.4 123.84,103.07 124.54,102.37 106.87,84.69 107.57,83.98 125.25,101.66 125.96,100.95 108.28,83.28 108.99,82.57 124.54,98.12 128.79,98.12 130.2,96.71 130.2,92.47 114.64,76.91 115.35,76.2 133.03,93.88 133.74,93.17 116.06,75.5 116.77,74.79 134.44,92.47 135.15,91.76 117.47,74.08 118.18,73.38 135.86,91.05 136.56,90.35 118.89,72.67 119.59,71.96 137.27,89.64 137.98,88.93 120.3,71.25 121.01,70.55 138.69,88.22 139.39,87.52 121.72,69.84 122.42,69.13 140.1,86.81 140.81,86.1 122.42,67.72 101.92,88.22 102.62,88.93 103.33,88.22 121.01,105.9
GND on LAYER2 (solid shape): 91.6,88.24 92.31,88.95 92.99,88.27 93.03,88.27 72.51,67.74 71.8,68.44 54.12,86.12 54.83,86.83 72.51,69.15 73.21,69.86 55.54,87.54 56.24,88.24 73.92,70.57 74.63,71.27 56.95,88.95 57.66,89.66 75.34,71.98 76.04,72.69 58.37,90.36 59.07,91.07 76.75,73.39 77.46,74.1 59.78,91.78 60.49,92.49 78.16,74.81 78.87,75.52 61.19,93.19 61.9,93.9 79.58,76.22 80.28,76.93 64.73,92.49 64.73,96.73 66.14,98.14 70.39,98.14 85.94,82.59 86.65,83.29 68.97,100.97 69.68,101.68 87.36,84 88.06,84.71 70.39,102.39 71.09,103.09 88.77,85.42 89.48,86.12 71.8,103.8 72.51,104.51 90.19,86.83 90.9,87.55 73.22,105.22 73.92,105.92
GND on LAYER2 (solid shape): 45.71,40.82 23.08,18.19 22.37,18.9 4.64,36.64 5.34,37.34 23.08,19.61 23.79,20.31 6.05,38.05 6.76,38.76 24.49,21.02 25.2,21.73 7.46,39.46 8.17,40.17 25.91,22.44 26.61,23.14 8.88,40.88 9.59,41.58 27.32,23.85 28.03,24.56 10.29,42.29 11,43 28.73,25.27 29.44,25.97 11.71,43.71 12.41,44.42 30.15,26.68 30.86,27.39 15.3,42.94 15.3,47.19 16.71,48.6 20.96,48.6 36.51,33.04 37.22,33.75 19.49,51.49 20.19,52.19 37.93,34.46 38.63,35.16 20.9,52.9 21.61,53.61 39.34,35.87 40.05,36.58 22.31,54.31 23.02,55.02 40.76,37.29 41.46,37.99 23.73,55.73 24.44,56.44 42.17,38.7 42.88,39.41 25.14,57.14 25.85,57.85 43.58,40.11 44.29,40.82 26.56,58.56 27.26,59.26
GND on LAYER2 (solid shape): 70.39,65.62 47.76,42.99 47.05,43.7 29.37,61.37 30.08,62.08 47.76,44.4 48.47,45.11 30.79,62.79 31.49,63.5 49.17,45.82 49.88,46.52 32.2,64.2 32.91,64.91 50.59,47.23 51.29,47.94 33.62,65.62 34.32,66.32 52,48.65 52.71,49.35 35.03,67.03 35.74,67.74 53.41,50.06 54.12,50.77 36.45,68.44 37.15,69.15 54.83,51.47 55.54,52.18 39.98,67.74 39.98,71.98 41.39,73.39 45.64,73.39 61.19,57.84 61.9,58.55 44.22,76.22 44.93,76.93 62.61,59.25 63.31,59.96 45.64,77.64 46.34,78.34 64.02,60.67 64.73,61.37 47.05,79.05 47.76,79.76 65.44,62.08 66.14,62.79 48.47,80.47 49.17,81.17 66.85,63.5 67.56,64.2 49.88,81.88 50.59,82.59 68.26,64.91 68.97,65.62 51.29,83.29 52,84
GND on LAYER2 (solid shape): 143.64,83.28 125.96,65.6 126.66,64.89 144.34,82.57 145.05,81.86 127.37,64.18 128.08,63.48 145.76,81.15 146.46,80.45 128.79,62.77 129.49,62.06 147.17,79.74 147.88,79.03 130.2,61.36 130.91,60.65 148.59,78.33 149.29,77.62 131.62,59.94 132.32,59.23 150,76.91 150.71,76.2 133.03,58.53 133.74,57.82 149.29,73.38 153.53,73.38 154.95,71.96 154.95,67.72 139.39,52.16 140.1,51.46 157.78,69.13 158.49,68.43 140.81,50.75 141.51,50.04 159.19,67.72 159.9,67.01 142.22,49.33 142.93,48.63 160.61,66.31 161.31,65.6 143.64,47.92 144.34,47.21 162.02,64.89 162.73,64.18 145.05,46.51 145.76,45.8 163.44,63.48 164.14,62.77 146.46,45.09 147.17,44.39 164.85,62.06 165.56,61.36 147.88,43.68 147.17,42.97 124.54,65.6 142.93,83.98
GND on LAYER2 (solid shape): 168.38,58.53 150.71,40.85 151.41,40.14 169.09,57.82 169.8,57.11 152.12,39.44 152.83,38.73 170.51,56.41 171.21,55.7 153.53,38.02 154.24,37.31 171.92,54.99 172.63,54.28 154.95,36.61 155.66,35.9 173.33,53.58 174.04,52.87 156.36,35.19 157.07,34.48 174.75,52.16 175.46,51.46 157.78,33.78 158.49,33.07 174.04,48.63 178.28,48.63 179.7,47.21 179.7,42.97 164.14,27.41 164.85,26.71 182.53,44.39 183.23,43.68 165.56,26 166.26,25.29 183.94,42.97 184.65,42.26 166.97,24.59 167.68,23.88 185.35,41.56 186.06,40.85 168.38,23.17 169.09,22.46 186.77,40.14 187.48,39.44 169.8,21.76 170.51,21.05 188.18,38.73 188.89,38.02 171.21,20.34 171.92,19.64 189.6,37.31 190.31,36.61 172.63,18.93 171.92,18.22 149.29,40.85 167.68,59.23
GND on LAYER3 (solid shape): 17.07,46.24 17.07,44.97 30.01,32.03 28.45,30.47 28.1,30.83 29.3,32.03 16.57,44.76 16.57,46.17 14.45,48.29 4.13,37.97 3.85,38.25 14.45,48.86
GND on LAYER3 (solid shape): 25.91,59.75 15.59,49.42 17.71,47.3 19.12,47.3 31.85,34.57 33.05,35.78 33.4,35.42 31.85,33.87 18.91,46.81 17.64,46.81 15.02,49.42 25.63,60.03
GND on LAYER3 (solid shape): 41.82,70.99 41.82,69.72 54.76,56.78 53.2,55.22 52.85,55.58 54.05,56.78 41.32,69.5 41.32,70.92 39.2,73.04 28.88,62.72 28.6,63 39.2,73.61
GND on LAYER3 (solid shape): 50.66,84.5 40.33,74.17 42.45,72.05 43.87,72.05 56.6,59.32 57.8,60.53 58.15,60.17 56.6,58.62 43.66,71.56 42.38,71.56 39.77,74.17 50.38,84.78
GND on LAYER3 (solid shape): 66.57,95.74 66.57,94.47 79.51,81.53 77.95,79.97 77.6,80.32 78.8,81.53 66.07,94.25 66.07,95.67 63.95,97.79 53.63,87.47 53.34,87.75 63.95,98.36
GND on LAYER3 (solid shape): 75.41,109.25 65.08,98.92 67.2,96.8 68.62,96.8 81.35,84.07 82.55,85.27 82.9,84.92 81.35,83.36 68.41,96.31 67.13,96.31 64.52,98.92 75.12,109.53
GND on LAYER3 (solid shape): 130.41,98.9 127.8,96.29 126.52,96.29 113.58,83.35 112.03,84.9 112.38,85.25 113.58,84.05 126.31,96.78 127.73,96.78 129.85,98.9 119.52,109.23 119.81,109.51
GND on LAYER3 (solid shape): 141.59,87.73 141.3,87.45 130.98,97.77 128.86,95.65 128.86,94.24 116.13,81.51 117.33,80.31 116.98,79.95 115.42,81.51 128.36,94.45 128.36,95.72 130.98,98.34
GND on LAYER3 (solid shape): 155.16,74.15 152.55,71.54 151.27,71.54 138.33,58.6 136.78,60.15 137.13,60.51 138.33,59.31 151.06,72.03 152.47,72.03 154.6,74.15 144.27,84.48 144.56,84.76
GND on LAYER3 (solid shape): 166.33,62.98 166.05,62.7 155.73,73.02 153.61,70.9 153.61,69.49 140.88,56.76 142.08,55.56 141.73,55.2 140.17,56.76 153.11,69.7 153.11,70.97 155.73,73.59
GND on LAYER3 (solid shape): 179.91,49.41 177.29,46.79 176.02,46.79 163.08,33.85 161.53,35.4 161.88,35.76 163.08,34.56 175.81,47.28 177.22,47.28 179.34,49.41 169.02,59.73 169.3,60.01
GND on LAYER3 (solid shape): 191.08,38.23 190.8,37.95 180.48,48.27 178.35,46.15 178.35,44.74 165.63,32.01 166.83,30.81 166.48,30.45 164.92,32.01 177.86,44.95 177.86,46.22 180.48,48.84
GND on LAYER5 (solid shape): 94.42,91.05 95.13,91.76 85.87,101.02 86.58,101.73 95.84,92.47 96.55,93.17 89.36,100.36 90.07,101.07 97.96,93.17 94.44,89.66 82.3,101.8 82.99,102.49
GND on LAYER5 (solid shape): 112.64,101.86 100.48,89.69 96.94,93.23 104.83,101.12 105.54,100.41 98.35,93.23 99.06,92.52 108.37,101.83 109.08,101.12 99.77,91.81 100.49,91.09 111.95,102.55
GND on LAYER5 (solid shape): 93.04,89.67 93.75,90.38 82.31,101.81 83,102.5 95.14,90.36 91.62,86.84 90.92,87.55 73.24,105.22 73.93,105.92 91.61,88.24 92.33,88.96 74.66,106.64 75.36,107.35
GND on LAYER5 (solid shape): 120.3,106.64 102.62,88.96 103.34,88.24 121.02,105.92 121.71,105.22 104.03,87.55 103.33,86.84 99.79,90.38 111.96,102.54 112.65,101.85 101.19,90.39 101.91,89.67 119.59,107.35
GND on LAYER5 (solid shape): 23.72,18.95 20.18,15.41 19.47,16.12 1.8,33.8 2.5,34.5 20.18,16.83 20.89,17.53 3.21,35.21 3.92,35.92 21.59,18.24 22.3,18.95 4.62,36.62 5.33,37.33
GND on LAYER5 (solid shape): 47.76,44.4 48.47,43.7 44.93,40.16 44.22,40.87 26.55,58.55 27.25,59.25 44.93,41.58 45.64,42.28 27.96,59.96 28.67,60.67 46.34,42.99 47.05,43.7 29.37,61.37 30.08,62.08
GND on LAYER5 (solid shape): 72.51,69.15 73.21,68.44 69.68,64.91 51.29,83.29 52,84 69.68,66.32 70.39,67.03 52.71,84.71 53.41,85.42 71.09,67.74 71.8,68.44 54.12,86.12 54.83,86.83
GND on LAYER5 (solid shape): 140.81,86.1 123.13,68.43 123.84,67.72 141.51,85.4 142.22,84.69 124.54,67.01 125.25,66.31 142.93,83.98 143.64,83.28 125.25,64.89 121.72,68.43 122.42,69.13 140.1,86.81
GND on LAYER5 (solid shape): 165.56,61.36 147.88,43.68 148.59,42.97 166.26,60.65 166.97,59.94 149.29,42.26 150,41.56 167.68,59.23 168.38,58.53 150,40.14 146.46,43.68 147.17,44.39 164.85,62.06
GND on LAYER5 (solid shape): 190.35,36.61 172.68,18.93 173.38,18.22 191.06,35.9 191.77,35.19 174.09,17.52 174.8,16.81 192.48,34.48 193.18,33.78 175.51,16.1 174.8,15.39 171.26,18.93 189.65,37.31
GND on LAYER5 (solid shape): 121.71,105.21 104.03,87.53 104.75,86.81 122.42,104.49 123.13,103.78 105.45,86.1 106.16,85.4 123.84,103.07 124.54,102.37 106.87,84.69 107.57,83.98 125.25,101.66 125.96,100.95 108.28,83.28 108.99,82.57 124.54,98.12 128.79,98.12 130.2,96.71 130.2,92.47 114.64,76.91 115.35,76.2 133.03,93.88 133.74,93.17 116.06,75.5 116.77,74.79 134.44,92.47 135.15,91.76 117.47,74.08 118.18,73.38 135.86,91.05 136.56,90.35 118.89,72.67 119.59,71.96 137.27,89.64 137.98,88.93 120.3,71.25 121.01,70.55 138.69,88.22 139.39,87.52 121.72,69.84 122.42,69.13 140.1,86.81 140.81,86.1 122.42,67.72 101.92,88.22 102.62,88.93 103.33,88.22 121.01,105.9
GND on LAYER5 (solid shape): 91.6,88.24 92.31,88.95 92.99,88.27 93.03,88.27 72.51,67.74 71.8,68.44 54.12,86.12 54.83,86.83 72.51,69.15 73.21,69.86 55.54,87.54 56.24,88.24 73.92,70.57 74.63,71.27 56.95,88.95 57.66,89.66 75.34,71.98 76.04,72.69 58.37,90.36 59.07,91.07 76.75,73.39 77.46,74.1 59.78,91.78 60.49,92.49 78.16,74.81 78.87,75.52 61.19,93.19 61.9,93.9 79.58,76.22 80.28,76.93 64.73,92.49 64.73,96.73 66.14,98.14 70.39,98.14 85.94,82.59 86.65,83.29 68.97,100.97 69.68,101.68 87.36,84 88.06,84.71 70.39,102.39 71.09,103.09 88.77,85.42 89.48,86.12 71.8,103.8 72.51,104.51 90.19,86.83 90.9,87.55 73.22,105.22 73.92,105.92
GND on LAYER5 (solid shape): 44.93,41.58 45.64,40.87 23.01,18.24 4.62,36.62 5.33,37.33 23.01,19.65 23.72,20.36 6.04,38.04 6.75,38.75 24.42,21.07 25.13,21.78 7.45,39.45 8.16,40.16 25.84,22.48 26.55,23.19 8.87,40.87 9.57,41.58 27.25,23.9 27.96,24.6 10.28,42.28 10.99,42.99 28.67,25.31 29.37,26.02 11.7,43.7 12.4,44.4 30.08,26.73 30.79,27.43 15.23,42.99 15.23,47.23 16.65,48.65 20.89,48.65 36.45,33.09 37.15,33.8 19.47,51.47 20.18,52.18 37.86,34.5 38.57,35.21 20.89,52.89 21.59,53.59 39.27,35.92 39.98,36.62 22.3,54.3 23.01,55.01 40.69,37.33 41.39,38.04 23.72,55.72 24.42,56.42 42.1,38.75 42.81,39.45 25.13,57.13 25.84,57.84 43.52,40.16 44.22,40.87 26.55,58.55 27.25,59.25
GND on LAYER5 (solid shape): 70.39,65.62 47.76,42.99 47.05,43.7 29.37,61.37 30.08,62.08 47.76,44.4 48.47,45.11 30.79,62.79 31.49,63.5 49.17,45.82 49.88,46.52 32.2,64.2 32.91,64.91 50.59,47.23 51.29,47.94 33.62,65.62 34.32,66.32 52,48.65 52.71,49.35 35.03,67.03 35.74,67.74 53.41,50.06 54.12,50.77 36.45,68.44 37.15,69.15 54.83,51.47 55.54,52.18 39.98,67.74 39.98,71.98 41.39,73.39 45.64,73.39 61.19,57.84 61.9,58.55 44.22,76.22 44.93,76.93 62.61,59.25 63.31,59.96 45.64,77.64 46.34,78.34 64.02,60.67 64.73,61.37 47.05,79.05 47.76,79.76 65.44,62.08 66.14,62.79 48.47,80.47 49.17,81.17 66.85,63.5 67.56,64.2 49.88,81.88 50.59,82.59 68.26,64.91 68.97,65.62 51.29,83.29 52,84
GND on LAYER5 (solid shape): 143.64,83.28 125.96,65.6 126.66,64.89 144.34,82.57 145.05,81.86 127.37,64.18 128.08,63.48 145.76,81.15 146.46,80.45 128.79,62.77 129.49,62.06 147.17,79.74 147.88,79.03 130.2,61.36 130.91,60.65 148.59,78.33 149.29,77.62 131.62,59.94 132.32,59.23 150,76.91 150.71,76.2 133.03,58.53 133.74,57.82 149.29,73.38 153.53,73.38 154.95,71.96 154.95,67.72 139.39,52.16 140.1,51.46 157.78,69.13 158.49,68.43 140.81,50.75 141.51,50.04 159.19,67.72 159.9,67.01 142.22,49.33 142.93,48.63 160.61,66.31 161.31,65.6 143.64,47.92 144.34,47.21 162.02,64.89 162.73,64.18 145.05,46.51 145.76,45.8 163.44,63.48 164.14,62.77 146.46,45.09 147.17,44.39 164.85,62.06 165.56,61.36 147.88,43.68 147.17,42.97 124.54,65.6 142.93,83.98
GND on LAYER5 (solid shape): 168.38,58.53 150.71,40.85 151.41,40.14 169.09,57.82 169.8,57.11 152.12,39.44 152.83,38.73 170.51,56.41 171.21,55.7 153.53,38.02 154.24,37.31 171.92,54.99 172.63,54.28 154.95,36.61 155.66,35.9 173.33,53.58 174.04,52.87 156.36,35.19 157.07,34.48 174.75,52.16 175.46,51.46 157.78,33.78 158.49,33.07 174.04,48.63 178.28,48.63 179.7,47.21 179.7,42.97 164.14,27.41 164.85,26.71 182.53,44.39 183.23,43.68 165.56,26 166.26,25.29 183.94,42.97 184.65,42.26 166.97,24.59 167.68,23.88 185.35,41.56 186.06,40.85 168.38,23.17 169.09,22.46 186.77,40.14 187.48,39.44 169.8,21.76 170.51,21.05 188.18,38.73 188.89,38.02 171.21,20.34 171.92,19.64 189.6,37.31 190.31,36.61 172.63,18.93 171.92,18.22 149.29,40.85 167.68,59.23
GND on TOP: 35.15,0.4 19.7,15.85 97.4,93.55 175.15,15.8 175.15,15.7 159.85,0.4 ; 1 cut-out
GND on BOTTOM: 35.15,0.4 19.7,15.85 97.4,93.55 175.15,15.8 175.15,15.7 159.85,0.4 ; 1 cut-out
GND on LAYER2, LAYER5: 35.15,0.4 19.7,15.85 97.4,93.55 175.15,15.8 175.15,15.7 159.85,0.4
GND2 on LAYER2 (solid shape): 89.92,101.17 89.23,100.48 78.85,110.85 79.55,111.55
GND2 on LAYER5 (solid shape): 89.92,101.17 89.23,100.48 78.85,110.85 79.55,111.55
GND3 on LAYER2 (solid shape): 116.02,110.93 105.67,100.58 104.97,101.28 115.33,111.62
GND3 on LAYER5 (solid shape): 116.02,110.93 105.67,100.58 104.97,101.28 115.33,111.62
ANT1 on LAYER4 (solid shape): 32.2,34.22 31.85,33.87 29.87,35.84 29.77,35.95 29.65,36.06 18.91,46.81 17.78,46.81 17.07,46.1 17.07,44.97 30.01,32.03 29.94,31.96 31.47,30.44 31.77,30.48 32.01,30.72 32.04,31.04 30.47,32.62 28.58,34.52 28.52,34.68 28.54,34.95 28.62,35.1 28.76,35.25 28.91,35.32 29.16,35.34 29.32,35.29 33.1,31.5 33.17,31.35 33.18,30.84 33.69,30.33 33.55,30.19 33.06,30.68 32.98,30.87 32.97,31.35 29.18,35.15 28.91,35.12 28.74,34.95 28.72,34.66 30.67,32.7 32.19,31.18 32.24,31.02 32.21,30.72 32.13,30.56 31.92,30.36 31.77,30.28 31.49,30.24 31.33,30.29 29.8,31.82 29.66,31.67 16.57,44.76 16.58,46.31 17.57,47.3 19.12,47.3
ANT2 on LAYER4 (solid shape): 56.95,58.97 56.59,58.61 54.62,60.59 54.51,60.69 54.4,60.81 43.66,71.56 42.53,71.55 41.82,70.85 41.82,69.72 54.76,56.78 54.69,56.71 56.22,55.19 56.51,55.23 56.76,55.47 56.79,55.79 55.22,57.37 53.33,59.27 53.27,59.43 53.29,59.7 53.36,59.85 53.51,60 53.66,60.07 53.91,60.09 54.07,60.04 57.85,56.25 57.92,56.1 57.94,55.58 58.44,55.08 58.29,54.94 57.81,55.43 57.73,55.62 57.72,56.1 53.93,59.89 53.66,59.87 53.49,59.7 53.47,59.41 55.42,57.45 56.94,55.93 56.99,55.77 56.96,55.47 56.88,55.31 56.67,55.11 56.52,55.03 56.24,54.99 56.08,55.04 54.55,56.57 54.41,56.42 41.32,69.5 41.33,71.06 42.32,72.05 43.87,72.05
ANT3 on LAYER4 (solid shape): 81.7,83.72 81.34,83.36 79.37,85.34 79.26,85.44 79.15,85.56 68.41,96.31 67.28,96.3 66.57,95.59 66.57,94.47 79.51,81.53 79.44,81.46 80.96,79.94 81.26,79.98 81.51,80.22 81.54,80.54 79.97,82.12 78.08,84.02 78.02,84.17 78.04,84.45 78.11,84.6 78.25,84.74 78.41,84.82 78.66,84.84 78.82,84.78 82.6,81 82.67,80.84 82.69,80.32 83.18,79.83 83.04,79.69 82.55,80.18 82.47,80.36 82.47,80.85 78.68,84.64 78.41,84.62 78.24,84.45 78.22,84.16 80.17,82.2 81.68,80.68 81.74,80.52 81.71,80.21 81.63,80.06 81.42,79.86 81.27,79.78 80.99,79.74 80.83,79.79 79.3,81.32 79.15,81.17 66.07,94.25 66.08,95.81 67.06,96.8 68.62,96.8
ANT4 on LAYER4 (solid shape): 127.87,96.78 128.86,95.79 128.86,94.24 115.77,81.16 115.42,81.51 117.39,83.48 117.5,83.59 117.62,83.7 128.36,94.45 128.36,95.58 127.65,96.29 126.52,96.29 113.58,83.35 113.52,83.41 111.99,81.89 112.04,81.59 112.28,81.35 112.6,81.31 114.18,82.88 116.07,84.78 116.23,84.83 116.5,84.81 116.66,84.74 116.8,84.6 116.88,84.44 116.9,84.19 116.84,84.03 113.06,80.25 112.9,80.19 112.4,80.18 111.89,79.67 111.75,79.81 112.23,80.3 112.42,80.38 112.91,80.39 116.7,84.18 116.67,84.44 116.51,84.61 116.22,84.64 114.26,82.68 112.74,81.17 112.58,81.11 112.27,81.15 112.12,81.22 111.91,81.43 111.84,81.59 111.79,81.86 111.85,82.03 113.38,83.55 113.23,83.7 126.31,96.78
ANT5 on LAYER4 (solid shape): 152.62,72.03 153.6,71.04 153.61,69.49 140.52,56.41 140.17,56.76 142.25,58.84 142.37,58.95 153.11,69.7 153.11,70.83 152.4,71.54 151.27,71.54 138.33,58.6 138.27,58.66 136.74,57.14 136.79,56.84 137.03,56.6 137.35,56.56 138.93,58.13 140.82,60.03 140.98,60.09 141.25,60.06 141.41,59.99 141.55,59.85 141.62,59.7 141.65,59.45 141.59,59.29 137.81,55.5 137.65,55.44 137.13,55.42 136.64,54.92 136.49,55.06 136.98,55.55 137.17,55.63 137.66,55.64 141.45,59.43 141.42,59.7 141.25,59.86 140.96,59.89 139.01,57.93 137.49,56.42 137.33,56.36 137.02,56.4 136.87,56.47 136.66,56.69 136.59,56.84 136.54,57.12 136.59,57.28 138.12,58.81 137.98,58.95 151.06,72.03
ANT6 on LAYER4 (solid shape): 177.37,47.28 178.35,46.29 178.35,44.74 165.27,31.66 164.92,32.01 166.89,33.99 167,34.09 167.11,34.21 177.86,44.95 177.86,46.08 177.15,46.79 176.02,46.79 163.08,33.85 163.01,33.91 161.49,32.39 161.54,32.09 161.77,31.85 162.09,31.81 163.68,33.38 165.57,35.28 165.73,35.34 166,35.32 166.16,35.24 166.3,35.1 166.37,34.95 166.4,34.7 166.34,34.54 162.56,30.75 162.4,30.69 161.88,30.67 161.38,30.17 161.24,30.31 161.73,30.8 161.92,30.88 162.41,30.89 166.2,34.68 166.17,34.95 166,35.12 165.71,35.14 163.76,33.18 162.24,31.67 162.07,31.62 161.77,31.65 161.62,31.72 161.41,31.94 161.34,32.09 161.29,32.37 161.34,32.53 162.87,34.06 162.73,34.2 175.81,47.28
Net_10 on LAYER5 (solid shape): 118.88,108.08 112.81,102 112.11,102.7 118.18,108.78
Net_11 on LAYER5 (solid shape): 117.45,109.5 109.25,101.3 108.55,102 116.75,110.2
Net_14 on LAYER5 (solid shape): 86.4,101.9 85.7,101.2 77.45,109.45 78.15,110.15
Net_15 on LAYER5 (solid shape): 82.83,102.67 82.13,101.98 76.05,108.05 76.75,108.75
Net_16 on LAYER2 (solid shape): 82.83,102.67 82.13,101.98 76.05,108.05 76.75,108.75
Net_16 on LAYER2 (solid shape): 118.88,108.08 112.81,102 112.11,102.7 118.18,108.78
Net_17 on LAYER2 (solid shape): 86.4,101.9 85.7,101.2 77.45,109.45 78.15,110.15
Net_17 on LAYER2 (solid shape): 117.45,109.5 109.25,101.3 108.55,102 116.75,110.2

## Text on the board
Ref Des/Silkscreen Bottom: J2 | J4 | DIO7 | DIO6 | DIO28 | DIO27 | DIO30 | DIO29 | J3 | J1 | BOOSTXL-AoA | MCU035 Rev.A | Angle Of Arrival 2.4 GHz
User.Comments: RED | 0.4 mm | 0.94 mm +/- 10%
Ref Des/Silkscreen Top: MCU035 Rev.A
XSECTION_CHART: *  SURFACE - AIR 0 MM | * FILMMASKTOP MASK - POLYIMIDE 0.015 MM | * SOLDERMASK_TOP MASK - POLYIMIDE 0.025 - 0.035 MM | L1 TOP CONDUCTOR - COPPER 0.035 MM | *  DIELECTRIC - FR-4 0.1 MM | L2 LAYER2 CONDUCTOR - COPPER 0.018 MM | *  DIELECTRIC - FR-4 0.2 MM | L3 LAYER3 CONDUCTOR - COPPER 0.018 MM | L4 LAYER4 CONDUCTOR - COPPER 0.018 MM | L5 LAYER5 CONDUCTOR - COPPER 0.018 MM | L6 BOTTOM CONDUCTOR - COPPER 0.035 MM | * SOLDERMASK_BOTTOM MASK - POLYIMIDE 0.025 - 0.035 MM | * FILMMASKBOTTOM MASK - POLYIMIDE 0.015 MM | DESIGN CROSS SECTION CHART | ___________________________ | TOTAL THICKNESS 0.922 - 942 MM | 1-6
DIMENSION: R 0.5 | All dimensions are in millimeters
COMPVAL_TYPE_TOP: J2 | J4 | DIO6 | DIO7 | DIO30 | DIO29 | DIO28 | DIO27 | J3 | J1 | Angle Of Arrival 2.4 GHz | BOOSTXL-AoA | A1.1 | A1.2 | A1.3 | A2.1 | A2.2 | A2.3
